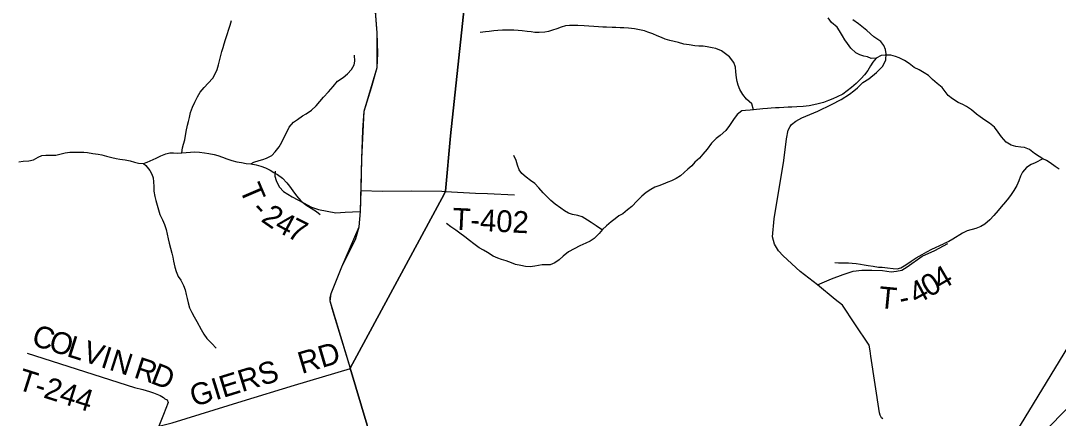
# Model space of a CAD drawing. Extents: x 0 to 34, y 0 to 22.
# Drawn here: x 3.817 to 6.52, y 16.76 to 17.795 of the extents above; entities that cross this region are included whole.
import ezdxf

# ---------------------------------------------------------------- set-up
doc = ezdxf.new("R2010")
doc.units = 0
for name, color, linetype in [('Default', 7, 'Continuous'), ('GM_X_County_Road', 7, 'Continuous'), ('GM_X_Minor_River', 7, 'Continuous'), ('GM_X_State_Route', 7, 'Continuous'), ('GM_X_Township_Road', 7, 'Continuous'), ('GM_X_Township_Road_Text', 7, 'Continuous'), ('SH_Text', 7, 'Continuous')]:
    doc.layers.add(name, color=color, linetype=linetype)

msp = doc.modelspace()

# ---------------------------------------------------------------- linework, layer by layer
at = {"layer": 'Default'}
for p, q in [((4.7457, 17.7634), (4.7334, 17.9364)), ((4.7459, 17.673), (4.7457, 17.7634)), ((4.7121, 17.5596), (4.7459, 17.673)), ((4.7062, 17.4355), (4.7121, 17.5596)), ((4.7021, 17.298), (4.7062, 17.4355)), ((4.6988, 17.2582), (4.7021, 17.298)), ((4.6542, 17.1544), (4.6988, 17.2582)), ((4.6258, 17.0849), (4.6542, 17.1544)), ((4.6235, 17.065), (4.6258, 17.0849)), ((4.676, 16.8898), (4.6235, 17.065)), ((4.7196, 16.7418), (4.676, 16.8898))]:
    msp.add_line(p, q, dxfattribs=at)
for points in [[(4.7194, 16.7424), (4.6758, 16.8903), (4.9207, 17.3435), (4.9239, 17.3511), (4.937, 17.4953), (4.9996, 18.0806), (5.0018, 18.1008), (4.7661, 18.9124), (4.831, 19.2363), (4.7641, 19.2419), (3.1893, 19.3592), (2.7961, 19.3885), (2.2, 19.4329), (2.2, 14)], [(9, 14), (9, 18.8941), (8.8762, 18.9027), (8.0305, 18.9725), (6.8442, 19.0679), (6.226, 19.1161), (5.8337, 19.1499), (5.3224, 19.1939), (5.1554, 19.2083), (4.831, 19.2363), (4.7661, 18.9124), (5.0018, 18.1008), (4.9996, 18.0806), (4.937, 17.4953), (4.9239, 17.3511), (4.9207, 17.3435), (4.6758, 16.8903), (4.7194, 16.7424)]]:
    msp.add_lwpolyline(points, dxfattribs=at)
at = {"layer": 'GM_X_County_Road'}
msp.add_lwpolyline([(6.0627, 16.7582), (6.0594, 16.7609), (6.0557, 16.7678), (6.0542, 16.7739), (6.0312, 16.9218), (6.0299, 16.9359), (6.0274, 16.9507), (5.9902, 17.0054), (5.9582, 17.0548), (5.9383, 17.0694), (5.8929, 17.1071), (5.8472, 17.1418), (5.8037, 17.1825), (5.7914, 17.196), (5.7803, 17.2135), (5.7755, 17.2322), (5.7795, 17.2792), (5.8046, 17.4312), (5.8123, 17.4877), (5.8164, 17.5096), (5.8214, 17.5198), (5.8252, 17.5243), (5.8363, 17.5333), (5.8523, 17.5415), (5.8937, 17.5589), (5.929, 17.5767), (5.9541, 17.5893), (5.9762, 17.6031), (5.9877, 17.6121), (5.9968, 17.6203), (6.011, 17.6342), (6.0262, 17.6432), (6.0464, 17.6596), (6.0625, 17.6765), (6.0706, 17.6928), (6.0715, 17.7087), (6.0698, 17.7201), (6.0653, 17.7304), (6.0575, 17.7408), (6.0391, 17.7531), (6.0215, 17.7692), (5.9998, 17.7862), (5.9844, 17.797)], dxfattribs=at)
at = {"layer": 'GM_X_Minor_River'}
for points in [[(4.2373, 17.4505), (4.2384, 17.4638), (4.2415, 17.4733), (4.2449, 17.4847), (4.2487, 17.506), (4.2514, 17.5227), (4.254, 17.5326), (4.2571, 17.5432), (4.2597, 17.5554), (4.265, 17.5694), (4.2711, 17.5831), (4.2776, 17.5968), (4.2844, 17.6086), (4.295, 17.6208), (4.3057, 17.6318), (4.3174, 17.6451), (4.325, 17.658), (4.3292, 17.6679), (4.3326, 17.6801), (4.3353, 17.6903), (4.3414, 17.7147), (4.3444, 17.7249), (4.3474, 17.7344), (4.3512, 17.7454), (4.3554, 17.7591), (4.3596, 17.7724), (4.3626, 17.7827), (4.3668, 17.7949)], [(5.7264, 17.5628), (5.7219, 17.578), (5.7082, 17.5902), (5.6984, 17.6027), (5.6908, 17.616), (5.6862, 17.6267), (5.6832, 17.6362), (5.6813, 17.6464), (5.6802, 17.662), (5.6787, 17.6734), (5.6749, 17.686), (5.6631, 17.7004), (5.6529, 17.7088), (5.6423, 17.716), (5.6279, 17.7221), (5.618, 17.7244), (5.6051, 17.7267), (5.5949, 17.7282), (5.5839, 17.7286), (5.5729, 17.7297), (5.5581, 17.7316), (5.5448, 17.7339), (5.5308, 17.7377), (5.5194, 17.7404), (5.5077, 17.7434), (5.4959, 17.7468), (5.4864, 17.751), (5.4754, 17.7552), (5.4637, 17.7609), (5.4512, 17.7651), (5.4417, 17.7681), (5.4292, 17.7712), (5.4163, 17.7738), (5.4003, 17.7754), (5.3882, 17.7761), (5.3787, 17.7765), (5.3677, 17.7769), (5.3575, 17.7769), (5.3431, 17.7776), (5.3336, 17.778), (5.3222, 17.7784), (5.3101, 17.7792), (5.2972, 17.7803), (5.2847, 17.7815), (5.2687, 17.7826), (5.2574, 17.7826), (5.2464, 17.7822), (5.2361, 17.7811), (5.2247, 17.778), (5.2134, 17.7739), (5.2023, 17.7697), (5.1921, 17.7666), (5.1826, 17.7647), (5.1675, 17.764), (5.1561, 17.7644), (5.1466, 17.7655), (5.1367, 17.7666), (5.1231, 17.7685), (5.1132, 17.7693), (5.1022, 17.7697), (5.0912, 17.7701), (5.0817, 17.7701), (5.0719, 17.7697), (5.0601, 17.7693), (5.0495, 17.7686), (5.0377, 17.767), (5.0279, 17.7659), (5.0138, 17.764)], [(6.0458, 17.6969), (6.0329, 17.6966), (6.0227, 17.7004), (6.0132, 17.7027), (6.003, 17.7061), (5.9924, 17.7114), (5.9799, 17.7236), (5.9708, 17.735), (5.9643, 17.7445), (5.9579, 17.7551), (5.9499, 17.768), (5.9435, 17.7779), (5.9294, 17.7901), (5.9203, 17.8019)], [(4.417, 17.4223), (4.4243, 17.4269), (4.4383, 17.4307), (4.4478, 17.4333), (4.4576, 17.4367), (4.4713, 17.4443), (4.4804, 17.4538), (4.4903, 17.4664), (4.4971, 17.4782), (4.5062, 17.4972), (4.5115, 17.5067), (4.5169, 17.5173), (4.5279, 17.5306), (4.5381, 17.5379), (4.551, 17.547), (4.5609, 17.5523), (4.5745, 17.5622), (4.5867, 17.5732), (4.5965, 17.5846), (4.6064, 17.5953), (4.6189, 17.6093), (4.6315, 17.6238), (4.6425, 17.6371), (4.6569, 17.647), (4.6686, 17.6561), (4.6793, 17.6679), (4.6861, 17.68), (4.688, 17.6895), (4.6872, 17.7047)], [(6.2176, 17.6209), (6.2043, 17.6315), (6.1926, 17.6414), (6.1816, 17.6521), (6.1706, 17.6593), (6.1577, 17.6665), (6.1448, 17.673), (6.1315, 17.6832), (6.1194, 17.6912), (6.1058, 17.6985), (6.0959, 17.7019), (6.0838, 17.7049), (6.069, 17.7053), (6.0587, 17.7045), (6.0458, 17.6969), (6.0367, 17.6867), (6.0307, 17.6772), (6.0242, 17.6654), (6.0147, 17.6536), (6.0064, 17.6441), (5.9938, 17.6312), (5.9809, 17.6205), (5.9703, 17.6122), (5.9586, 17.6038), (5.9441, 17.5966), (5.9328, 17.5916), (5.9217, 17.5871), (5.9085, 17.5821), (5.8948, 17.578), (5.8834, 17.5761), (5.8709, 17.5734), (5.8557, 17.5715), (5.8391, 17.5708), (5.8258, 17.57), (5.8163, 17.5696), (5.8053, 17.5689), (5.7932, 17.5681), (5.7829, 17.5677), (5.7719, 17.567), (5.7624, 17.5662), (5.7499, 17.5651), (5.7264, 17.5628), (5.7169, 17.562), (5.7055, 17.5613), (5.6957, 17.5601), (5.6835, 17.5502), (5.6741, 17.5373), (5.6634, 17.5221), (5.6539, 17.5088), (5.6395, 17.4963), (5.6289, 17.4879), (5.6167, 17.4757), (5.605, 17.4605), (5.594, 17.4476), (5.5852, 17.4373), (5.5735, 17.4267), (5.5651, 17.4172), (5.5549, 17.4085), (5.545, 17.3993), (5.5355, 17.3914), (5.5245, 17.3841), (5.5124, 17.378), (5.5029, 17.3742), (5.4908, 17.3697), (5.4798, 17.3651), (5.4691, 17.3617), (5.4589, 17.3556), (5.4464, 17.3476), (5.435, 17.3385), (5.4232, 17.3256), (5.4088, 17.3112), (5.3982, 17.3024), (5.3853, 17.2925), (5.3754, 17.2872), (5.3656, 17.2792), (5.3553, 17.2712), (5.3435, 17.261), (5.3329, 17.2515), (5.3242, 17.2412), (5.3109, 17.2283), (5.3007, 17.2211), (5.2893, 17.2154), (5.2741, 17.2089), (5.2593, 17.2013), (5.2438, 17.1929), (5.2301, 17.1823), (5.2199, 17.172), (5.2085, 17.1648), (5.1967, 17.1595), (5.1872, 17.1591), (5.1755, 17.1591), (5.166, 17.158), (5.1565, 17.1557), (5.144, 17.1545), (5.1319, 17.1553), (5.1201, 17.1576), (5.1061, 17.1606), (5.0958, 17.1644), (5.0822, 17.1694), (5.0697, 17.1732), (5.0602, 17.1766)], [(6.2708, 17.5767), (6.2589, 17.5815), (6.2444, 17.5916), (6.2326, 17.6002), (6.2176, 17.6209)], [(6.5221, 17.4082), (6.5118, 17.4154), (6.4988, 17.4251), (6.4889, 17.4307), (6.4793, 17.4355), (6.4698, 17.4415), (6.4583, 17.449), (6.4453, 17.4591), (6.4316, 17.4643), (6.4221, 17.4657), (6.4096, 17.4675), (6.397, 17.4708), (6.3844, 17.479), (6.3721, 17.4926), (6.3633, 17.505), (6.3533, 17.5178), (6.3407, 17.528), (6.3285, 17.5358), (6.3166, 17.5441), (6.307, 17.5519), (6.294, 17.5628), (6.2807, 17.5718), (6.2708, 17.5767)], [(3.8125, 17.4273), (3.8242, 17.4288), (3.8383, 17.43), (3.8504, 17.433), (3.8626, 17.4395), (3.8728, 17.444), (3.8827, 17.4452), (3.8952, 17.4444), (3.9088, 17.4452), (3.9331, 17.4505), (3.9452, 17.4524), (3.9589, 17.4528), (3.982, 17.4528), (3.9915, 17.4516), (4.0048, 17.4493), (4.0188, 17.447), (4.0287, 17.4455), (4.0412, 17.4421), (4.0545, 17.4383), (4.0658, 17.436), (4.0757, 17.4341), (4.0897, 17.4322), (4.1026, 17.4296), (4.114, 17.4265), (4.1242, 17.4239), (4.1371, 17.4235), (4.1466, 17.4265), (4.1705, 17.4372), (4.1823, 17.4429), (4.1952, 17.4482), (4.2054, 17.4505), (4.2149, 17.4508), (4.2267, 17.4501), (4.2373, 17.4505), (4.2483, 17.4516), (4.2597, 17.4527), (4.2699, 17.4531), (4.2832, 17.4527), (4.2957, 17.4512), (4.3071, 17.4489), (4.3211, 17.4463), (4.331, 17.4436), (4.3427, 17.4394), (4.3541, 17.4352), (4.3674, 17.431), (4.3806, 17.4276), (4.3928, 17.4253), (4.4049, 17.4234), (4.417, 17.4223), (4.4303, 17.42), (4.4432, 17.4158), (4.4546, 17.412), (4.4671, 17.4056), (4.4766, 17.3995)], [(5.3329, 17.2515), (5.3299, 17.2515), (5.3166, 17.2606), (5.3033, 17.2693), (5.2935, 17.2754), (5.2795, 17.2846), (5.2685, 17.288), (5.2548, 17.2906), (5.2442, 17.2937), (5.234, 17.2998), (5.2241, 17.307), (5.2097, 17.3173), (5.1983, 17.3268), (5.1782, 17.3469), (5.1672, 17.3595), (5.1562, 17.3709), (5.1452, 17.3785), (5.1343, 17.3872), (5.1225, 17.3967), (5.1157, 17.4062), (5.1115, 17.4184), (5.1077, 17.4313), (5.102, 17.4443)], [(6.4793, 17.4355), (6.4593, 17.4251), (6.4495, 17.4205), (6.437, 17.4124), (6.4269, 17.4001), (6.4216, 17.3898), (6.4172, 17.3784), (6.4116, 17.3662), (6.4045, 17.3528), (6.3974, 17.3425), (6.3898, 17.3329), (6.382, 17.323), (6.3714, 17.3104), (6.3632, 17.3008), (6.3523, 17.2878), (6.3414, 17.2763), (6.3282, 17.2648), (6.3183, 17.259), (6.3055, 17.2539), (6.2827, 17.2476), (6.2706, 17.2422), (6.245, 17.226), (6.2347, 17.2202), (6.2211, 17.2144)], [(4.1371, 17.4235), (4.1432, 17.4178), (4.1534, 17.4052), (4.1591, 17.3953), (4.1622, 17.3854), (4.1633, 17.3756), (4.1637, 17.363), (4.1644, 17.3512), (4.1671, 17.3375), (4.1697, 17.3269), (4.1727, 17.3144), (4.1761, 17.3022), (4.1799, 17.29), (4.1867, 17.2767), (4.1921, 17.2642), (4.1958, 17.2512), (4.1989, 17.2395), (4.2011, 17.2269), (4.2038, 17.2155), (4.2072, 17.2026), (4.211, 17.1897), (4.2136, 17.179), (4.2155, 17.1691), (4.2189, 17.1535), (4.2219, 17.1421), (4.2273, 17.1288), (4.2341, 17.1193), (4.2413, 17.1052), (4.2454, 17.0946), (4.2485, 17.0821), (4.2507, 17.0718), (4.2538, 17.0608), (4.2568, 17.0478), (4.2629, 17.0353), (4.2693, 17.0239), (4.2765, 17.0121), (4.2871, 16.9908), (4.2947, 16.9786), (4.3019, 16.9676), (4.3148, 16.9543), (4.3261, 16.9429)], [(4.4766, 17.3995), (4.4864, 17.3942), (4.4993, 17.3847), (4.5103, 17.3732), (4.5179, 17.3637), (4.5259, 17.3516), (4.5353, 17.339), (4.5471, 17.3261), (4.5604, 17.3154), (4.5736, 17.3067), (4.5877, 17.298), (4.5975, 17.2907)], [(5.0602, 17.1766), (5.0477, 17.1819), (5.0333, 17.1911), (5.0226, 17.1979), (5.0113, 17.2036), (4.998, 17.2143), (4.9866, 17.223), (4.9745, 17.2321), (4.9612, 17.242), (4.951, 17.2492), (4.9377, 17.2584), (4.926, 17.2667)], [(5.9378, 17.1655), (5.9473, 17.1643), (5.9731, 17.1643), (5.9833, 17.1639), (5.9932, 17.1632), (6.0046, 17.1613), (6.0144, 17.1597), (6.0247, 17.1578), (6.0376, 17.1556), (6.052, 17.1537), (6.0615, 17.1529), (6.0751, 17.1517), (6.0895, 17.1502), (6.0998, 17.1491), (6.1096, 17.1517), (6.1225, 17.1593), (6.1366, 17.1692), (6.1495, 17.178), (6.165, 17.1859), (6.1776, 17.1936), (6.1905, 17.2), (6.2211, 17.2144)]]:
    msp.add_lwpolyline(points, dxfattribs=at)
at = {"layer": 'GM_X_State_Route'}
for points in [[(4.676, 16.8898), (4.6315, 17.0374), (4.6235, 17.065), (4.6232, 17.0732), (4.6258, 17.0849), (4.6542, 17.1544), (4.6904, 17.2283), (4.6988, 17.2582), (4.7021, 17.298), (4.7044, 17.3531), (4.7062, 17.4355), (4.7088, 17.5099), (4.7121, 17.5596), (4.7312, 17.6208), (4.7459, 17.673), (4.7476, 17.7095), (4.7457, 17.7634), (4.7386, 17.8513), (4.7334, 17.9364), (4.7336, 18.0018), (4.7074, 18.0837), (4.7049, 18.0936)], [(4.7669, 16.6542), (4.7475, 16.6508), (4.7196, 16.7418), (4.676, 16.8898)]]:
    msp.add_lwpolyline(points, dxfattribs=at)
at = {"layer": 'GM_X_Township_Road'}
msp.add_line((5.0335, 17.3448), (5.1036, 17.3415), dxfattribs=at)
for points in [[(4.4799, 17.4028), (4.479, 17.3903), (4.483, 17.3785), (4.4859, 17.3712), (4.4915, 17.3617), (4.502, 17.3505), (4.5241, 17.3362), (4.5535, 17.3203), (4.5749, 17.3095), (4.5926, 17.3032), (4.6156, 17.2988), (4.6379, 17.2947), (4.6621, 17.2967), (4.6818, 17.2973), (4.7021, 17.298)], [(4.7044, 17.3531), (4.7588, 17.3511), (4.8359, 17.3516), (4.9141, 17.3507)], [(4.9141, 17.3507), (4.9241, 17.3506), (5.0015, 17.3463), (5.0335, 17.3448)], [(5.8929, 17.1071), (5.929, 17.1227), (5.9594, 17.1341), (5.9856, 17.1425), (6.008, 17.1457), (6.0344, 17.1458), (6.0624, 17.1443), (6.0847, 17.141), (6.0983, 17.1428), (6.1123, 17.1457), (6.126, 17.1542), (6.1657, 17.1819), (6.198, 17.1967), (6.2322, 17.2149)], [(3.8345, 16.9294), (4.1141, 16.8405), (4.1356, 16.835), (4.1526, 16.8294), (4.1603, 16.8269)], [(4.1773, 16.7396), (4.2115, 16.7483), (4.3943, 16.8043), (4.5306, 16.8465), (4.676, 16.8898)], [(4.1603, 16.8269), (4.1631, 16.8259), (4.1718, 16.8228), (4.1808, 16.8189), (4.1895, 16.8142), (4.1928, 16.8108), (4.1989, 16.8077), (4.2018, 16.8008), (4.1894, 16.7702), (4.1773, 16.7396)]]:
    msp.add_lwpolyline(points, dxfattribs=at)
at = {"layer": 'SH_Text'}
msp.add_lwpolyline([(6.2851, 16.5198), (6.9075, 17.1619), (6.9066, 17.5389)], close=True, dxfattribs=at)

# ---------------------------------------------------------------- texts
at = {"layer": 'GM_X_Township_Road_Text'}
for s, height, rotation, p in [('T', 0.0568, 293.1305, (4.3863, 17.357)), ('-', 0.0568, 312.8286, (4.4145, 17.3002)), ('2', 0.0568, 325.4781, (4.4407, 17.2741)), ('T-402', 0.05682, 357.1936, (4.941, 17.2511)), ('4', 0.0568, 331.9603, (4.4755, 17.2507)), ('7', 0.0568, 333.5465, (4.5079, 17.2334)), ('0', 0.0568, 31.0992, (6.1838, 17.0733)), ('4', 0.0568, 30.4033, (6.2137, 17.0913)), ('4', 0.0568, 28.3013, (6.1504, 17.0552)), ('T', 0.0568, 354.4715, (6.0499, 17.0473)), ('-', 0.0568, 12.1237, (6.1112, 17.0443)), ('C', 0.0568, 342.3254, (3.8427, 16.9517)), ('O', 0.0568, 342.3265, (3.8871, 16.9375)), ('L', 0.0568, 342.3254, (3.9348, 16.9223)), ('V', 0.0568, 342.3265, (3.9753, 16.9094)), ('I', 0.0568, 342.3295, (4.0229, 16.8942)), ('RD', 0.05682, 16.5575, (4.5493, 16.8751)), ('N', 0.0568, 342.3265, (4.0451, 16.8871)), ('R', 0.0568, 342.1044, (4.1094, 16.8667)), ('T-244', 0.05682, 342.3619, (3.8058, 16.8364)), ('D', 0.0568, 338.7208, (4.153, 16.8526)), ('GIERS', 0.05682, 17.1551, (4.2683, 16.7893))]:
    msp.add_text(s, height=height, rotation=rotation, dxfattribs=at).set_placement(p)

doc.saveas('drawing.dxf')
